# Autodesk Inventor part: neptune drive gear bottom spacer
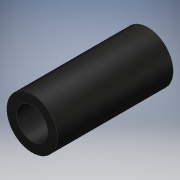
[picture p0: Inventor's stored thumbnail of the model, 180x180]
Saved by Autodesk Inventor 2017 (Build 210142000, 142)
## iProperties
Created: 2016-07
Part Number: neptune drive gear bottom spacer
Material: Generic
Document SubType Name: Modeling
Designer: Stan
Density: 1 g/cm^3
Appearance: Glossy - Black
Author: Stan
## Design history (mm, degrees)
sketch "Sketch1"
  geometry: C1 r 3.429 at (0, 0); C2 r 5.556 at (0, 0); 1 further point
  constraints: 2 centre point, 2 coincident
  dimensions: "d0" = 6.858 diameter of C1; "d1" = 11.1125 diameter of C2
extrude "Extrusion1" new body sketch "Sketch1" distance "d2" = 25.4; taper "d3" = 0 deg
body "Solid1"
